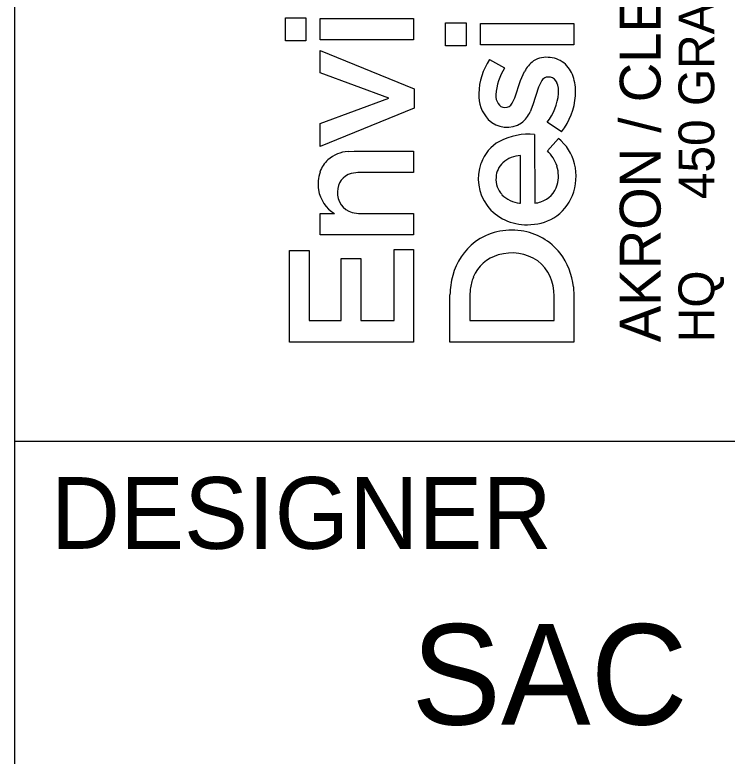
# Model space of a CAD drawing. Extents: x -0.6 to 34, y 0 to 22.
# Drawn here: x 32 to 32.993, y 2.061 to 3.094 of the extents above; entities that cross this region are included whole.
import ezdxf

# ---------------------------------------------------------------- set-up
doc = ezdxf.new("R2010")
doc.units = 0
doc.layers.add('SH_Cut_Line', color=7, linetype='Continuous')
doc.layers.add('SH_Data', color=7, linetype='Continuous')

msp = doc.modelspace()

# ---------------------------------------------------------------- linework, layer by layer
at = {"layer": 'SH_Cut_Line'}
for p, q in [((32.3771, 3.0582), (32.3771, 3.0903)), ((32.3771, 3.0903), (32.4054, 3.0903)), ((32.4054, 3.0903), (32.4054, 3.0582)), ((32.4254, 3.0594), (32.4254, 3.0893)), ((32.4254, 3.0893), (32.5557, 3.0893)), ((32.5557, 3.0893), (32.5557, 3.0594)), ((32.6005, 3.0511), (32.6005, 3.0832)), ((32.6005, 3.0832), (32.6289, 3.0832)), ((32.6289, 3.0832), (32.6289, 3.0511)), ((32.6489, 3.0523), (32.6489, 3.0822)), ((32.6489, 3.0822), (32.7792, 3.0822)), ((32.7792, 3.0822), (32.7792, 3.0523)), ((32.5557, 3.0594), (32.4254, 3.0594)), ((32.4054, 3.0582), (32.3771, 3.0582)), ((32.6289, 3.0511), (32.6005, 3.0511)), ((32.7792, 3.0523), (32.6489, 3.0523)), ((32.4254, 3.0133), (32.4254, 3.0446)), ((32.4254, 3.0446), (32.5567, 2.9913)), ((32.6615, 3.0321), (32.6827, 3.0203)), ((32.5212, 2.978), (32.4254, 3.0133)), ((32.7048, 3.0026), (32.7104, 3.0153)), ((32.6967, 2.9787), (32.7048, 3.0026)), ((32.7334, 3.001), (32.7298, 2.9933)), ((32.5567, 2.9913), (32.5567, 2.9644)), ((32.7298, 2.9933), (32.7221, 2.9688)), ((32.4254, 2.9429), (32.5212, 2.978)), ((32.693, 2.9712), (32.6967, 2.9787)), ((32.7221, 2.9688), (32.7182, 2.9592)), ((32.5567, 2.9644), (32.4254, 2.9109)), ((32.4254, 2.9109), (32.4254, 2.9429)), ((32.7621, 2.9314), (32.742, 2.9447)), ((32.7245, 2.9275), (32.7246, 2.8319)), ((32.7423, 2.9046), (32.7577, 2.922)), ((32.4644, 2.904), (32.4729, 2.9044)), ((32.4729, 2.9044), (32.5557, 2.9044)), ((32.5557, 2.9044), (32.5557, 2.8746)), ((32.7049, 2.8318), (32.7049, 2.8983)), ((32.5557, 2.8746), (32.4814, 2.8746)), ((32.7036, 2.8317), (32.7049, 2.8318)), ((32.4254, 2.7875), (32.4254, 2.8173)), ((32.4254, 2.8173), (32.4455, 2.8173)), ((32.4822, 2.8173), (32.5557, 2.8173)), ((32.5557, 2.8173), (32.5557, 2.7876)), ((32.5557, 2.7876), (32.4254, 2.7875)), ((32.383, 2.6379), (32.383, 2.766)), ((32.383, 2.766), (32.4101, 2.766)), ((32.4101, 2.766), (32.4101, 2.6683)), ((32.5286, 2.6683), (32.5286, 2.7672)), ((32.5286, 2.7672), (32.5557, 2.7672)), ((32.5557, 2.7672), (32.5557, 2.6379)), ((32.455, 2.6683), (32.455, 2.7549)), ((32.455, 2.7549), (32.4822, 2.7549)), ((32.4822, 2.7549), (32.4822, 2.6683)), ((32.6347, 2.7118), (32.6341, 2.7023)), ((32.7785, 2.715), (32.7792, 2.7021)), ((32.6064, 2.638), (32.6064, 2.704)), ((32.6341, 2.7023), (32.6341, 2.6684)), ((32.7515, 2.6683), (32.7515, 2.7024)), ((32.7792, 2.7021), (32.7792, 2.638)), ((32.4101, 2.6683), (32.455, 2.6683)), ((32.4822, 2.6683), (32.5286, 2.6683)), ((32.6341, 2.6684), (32.7515, 2.6683)), ((32.5557, 2.6379), (32.383, 2.6379)), ((32.7792, 2.638), (32.6064, 2.638))]:
    msp.add_line(p, q, dxfattribs=at)
for points in [[(32.3771, 3.0582), (32.3771, 3.0903), (32.4054, 3.0903), (32.4054, 3.0582)], [(32.4254, 3.0594), (32.4254, 3.0893), (32.5557, 3.0893), (32.5557, 3.0594)], [(32.6005, 3.0511), (32.6005, 3.0832), (32.6289, 3.0832), (32.6289, 3.0511)], [(32.6489, 3.0523), (32.6489, 3.0822), (32.7792, 3.0822), (32.7792, 3.0523)], [(32.4254, 2.9109), (32.4254, 2.9429), (32.5212, 2.978), (32.4254, 3.0133), (32.4254, 3.0446), (32.5567, 2.9913), (32.5567, 2.9644)], [(32.383, 2.6379), (32.383, 2.766), (32.4101, 2.766), (32.4101, 2.6683), (32.455, 2.6683), (32.455, 2.7549), (32.4822, 2.7549), (32.4822, 2.6683), (32.5286, 2.6683), (32.5286, 2.7672), (32.5557, 2.7672), (32.5557, 2.6379)]]:
    msp.add_lwpolyline(points, close=True, dxfattribs=at)
for points in [[(32.6615, 3.0321), (32.6827, 3.0203)], [(32.693, 2.9712), (32.6967, 2.9787), (32.7048, 3.0026), (32.7104, 3.0153)], [(32.7334, 3.001), (32.7298, 2.9933), (32.7221, 2.9688), (32.7182, 2.9592)], [(32.7621, 2.9314), (32.742, 2.9447)], [(32.7245, 2.9275), (32.7246, 2.8319)], [(32.7423, 2.9046), (32.7577, 2.922)], [(32.4644, 2.904), (32.4729, 2.9044), (32.5557, 2.9044), (32.5557, 2.8746), (32.4814, 2.8746)], [(32.7036, 2.8317), (32.7049, 2.8318), (32.7049, 2.8983)], [(32.4254, 2.7875), (32.4254, 2.8173), (32.4455, 2.8173)], [(32.4822, 2.8173), (32.5557, 2.8173), (32.5557, 2.7876), (32.4254, 2.7875)], [(32.7785, 2.715), (32.7792, 2.7021), (32.7792, 2.638), (32.6064, 2.638)], [(32.6347, 2.7118), (32.6341, 2.7023), (32.6341, 2.6684), (32.7515, 2.6683), (32.7515, 2.7024)], [(32.6064, 2.638), (32.6064, 2.704)]]:
    msp.add_lwpolyline(points, dxfattribs=at)
for centre, radius, start, end in [((32.7364, 2.9826), 0.0897, 146.531, 178.7571), ((32.7364, 2.9826), 0.0897, 146.531, 178.7571), ((32.7466, 2.9971), 0.0405, 125.5118, 153.4159), ((32.7466, 2.9971), 0.0405, 125.5118, 153.4159), ((32.7406, 3.0026), 0.0326, 80.1719, 122.5197), ((32.7406, 3.0026), 0.0326, 80.1719, 122.5197), ((32.7428, 2.9982), 0.0367, 47.7934, 84.6892), ((32.7428, 2.9982), 0.0367, 47.7934, 84.6892), ((32.7452, 2.9789), 0.0749, 146.5112, 176.9101), ((32.7452, 2.9789), 0.0749, 146.5112, 176.9101), ((32.7379, 2.9946), 0.0427, 14.9966, 46.2063), ((32.7379, 2.9946), 0.0427, 14.9966, 46.2063), ((32.7438, 2.9963), 0.0114, 76.6609, 155.7053), ((32.7438, 2.9963), 0.0114, 76.6609, 155.7053), ((32.744, 2.9951), 0.0126, 21.5098, 78.5262), ((32.744, 2.9951), 0.0126, 21.5098, 78.5262), ((32.7259, 2.9877), 0.0321, 354.5726, 22.068), ((32.7259, 2.9877), 0.0321, 354.5726, 22.068), ((32.7104, 2.9867), 0.0712, 355.8306, 15.3914), ((32.7104, 2.9867), 0.0712, 355.8306, 15.3914), ((32.6967, 2.9824), 0.0501, 177.5366, 222.7932), ((32.6967, 2.9824), 0.0501, 177.5366, 222.7932), ((32.6931, 2.9823), 0.0228, 178.4747, 211.0868), ((32.6931, 2.9823), 0.0228, 178.4747, 211.0868), ((32.6825, 2.9915), 0.0757, 321.811, 354.7969), ((32.6825, 2.9915), 0.0757, 321.811, 354.7969), ((32.6895, 2.9882), 0.0922, 321.9777, 355.8738), ((32.6895, 2.9882), 0.0922, 321.9777, 355.8738), ((32.6833, 2.9767), 0.0115, 212.2368, 268.3777), ((32.6833, 2.9767), 0.0115, 212.2368, 268.3777), ((32.6834, 2.9759), 0.0107, 267.716, 333.7337), ((32.6834, 2.9759), 0.0107, 267.716, 333.7337), ((32.681, 2.9758), 0.0408, 308.0877, 335.9874), ((32.681, 2.9758), 0.0408, 308.0877, 335.9874), ((32.686, 2.9753), 0.0375, 225.9854, 302.4797), ((32.686, 2.9753), 0.0375, 225.9854, 302.4797), ((32.7152, 2.8441), 0.0838, 83.615, 118.2876), ((32.7152, 2.8441), 0.0838, 83.615, 118.2876), ((32.7024, 2.8691), 0.0558, 118.8308, 160.6244), ((32.7024, 2.8691), 0.0558, 118.8308, 160.6244), ((32.7174, 2.8717), 0.0644, 13.5336, 51.3615), ((32.7174, 2.8717), 0.0644, 13.5336, 51.3615), ((32.4687, 2.8543), 0.0499, 94.9696, 130.2225), ((32.4687, 2.8543), 0.0499, 94.9696, 130.2225), ((32.7038, 2.8656), 0.0549, 19.0357, 45.4406), ((32.7038, 2.8656), 0.0549, 19.0357, 45.4406), ((32.7079, 2.8561), 0.0424, 94.008, 130.8817), ((32.7079, 2.8561), 0.0424, 94.008, 130.8817), ((32.4635, 2.8626), 0.0402, 132.2219, 161.6818), ((32.4635, 2.8626), 0.0402, 132.2219, 161.6818), ((32.7104, 2.8661), 0.0644, 160.5201, 215.7831), ((32.7104, 2.8661), 0.0644, 160.5201, 215.7831), ((32.7005, 2.8663), 0.0298, 132.9851, 177.179), ((32.7005, 2.8663), 0.0298, 132.9851, 177.179), ((32.7107, 2.8697), 0.047, 344.6059, 17.007), ((32.7107, 2.8697), 0.047, 344.6059, 17.007), ((32.7064, 2.8692), 0.0758, 339.3542, 13.3785), ((32.7064, 2.8692), 0.0758, 339.3542, 13.3785), ((32.4787, 2.8582), 0.056, 162.2736, 187.7919), ((32.4787, 2.8582), 0.056, 162.2736, 187.7919), ((32.4748, 2.8487), 0.025, 103.6865, 182.2187), ((32.4748, 2.8487), 0.025, 103.6865, 182.2187), ((32.4811, 2.8286), 0.046, 89.6049, 105.3284), ((32.4811, 2.8286), 0.046, 89.6049, 105.3284), ((32.7017, 2.865), 0.0311, 175.0013, 223.283), ((32.7017, 2.865), 0.0311, 175.0013, 223.283), ((32.7224, 2.8671), 0.035, 288.0077, 343.5508), ((32.7224, 2.8671), 0.035, 288.0077, 343.5508), ((32.4703, 2.858), 0.0476, 188.962, 238.7037), ((32.4703, 2.858), 0.0476, 188.962, 238.7037), ((32.4773, 2.8456), 0.0276, 175.5854, 255.1439), ((32.4773, 2.8456), 0.0276, 175.5854, 255.1439), ((32.7089, 2.8736), 0.0423, 225.0619, 262.7974), ((32.7089, 2.8736), 0.0423, 225.0619, 262.7974), ((32.7189, 2.8652), 0.0626, 300.9427, 338.7323), ((32.7189, 2.8652), 0.0626, 300.9427, 338.7323), ((32.7247, 2.8522), 0.0202, 269.7003, 294.8711), ((32.7247, 2.8522), 0.0202, 269.7003, 294.8711), ((32.7125, 2.8705), 0.0687, 217.7452, 271.6543), ((32.7125, 2.8705), 0.0687, 217.7452, 271.6543), ((32.4818, 2.8595), 0.0422, 254.0916, 270.5284), ((32.4818, 2.8595), 0.0422, 254.0916, 270.5284), ((32.7155, 2.8724), 0.0706, 269.2048, 300.3341), ((32.7155, 2.8724), 0.0706, 269.2048, 300.3341), ((32.6923, 2.7079), 0.0864, 81.194, 125.9984), ((32.6923, 2.7079), 0.0864, 81.194, 125.9984), ((32.6946, 2.7113), 0.0827, 37.8521, 82.402), ((32.6946, 2.7113), 0.0827, 37.8521, 82.402), ((32.6939, 2.7089), 0.0865, 127.2362, 165.148), ((32.6939, 2.7089), 0.0865, 127.2362, 165.148), ((32.6889, 2.7078), 0.054, 106.1881, 157.3861), ((32.6889, 2.7078), 0.054, 106.1881, 157.3861), ((32.6928, 2.6986), 0.0639, 55.6727, 107.2093), ((32.6928, 2.6986), 0.0639, 55.6727, 107.2093), ((32.6859, 2.7057), 0.0931, 5.7333, 37.304), ((32.6859, 2.7057), 0.0931, 5.7333, 37.304), ((32.6929, 2.705), 0.0587, 357.4662, 52.2665), ((32.6929, 2.705), 0.0587, 357.4662, 52.2665), ((32.7143, 2.7028), 0.1078, 164.7861, 179.3704), ((32.7143, 2.7028), 0.1078, 164.7861, 179.3704), ((32.6983, 2.7039), 0.0641, 157.3571, 172.9275), ((32.6983, 2.7039), 0.0641, 157.3571, 172.9275)]:
    msp.add_arc(centre, radius, start, end, dxfattribs=at)
at = {"layer": 'SH_Data'}
for p, q in [((32, 0.5), (32, 21.5)), ((32, 2.5), (33.5, 2.5))]:
    msp.add_line(p, q, dxfattribs=at)

# ---------------------------------------------------------------- texts
at = {"layer": 'SH_Cut_Line'}
for s, height, p in [('450 GRANT ST., AKRON, OH  44311', 0.049846, (32.9749, 2.8374)), ('AKRON / CLEVELAND / COLUMBUS', 0.056969, (32.9001, 2.638)), ('HQ ', 0.04985, (32.9749, 2.638))]:
    msp.add_text(s, height=height, rotation=90, dxfattribs=at).set_placement(p)
for s, height, p in [('DESIGNER', 0.1, (32.05, 2.35)), ('SAC', 0.14, (32.5528, 2.105))]:
    msp.add_text(s, height=height, dxfattribs=at).set_placement(p)

doc.saveas('drawing.dxf')
